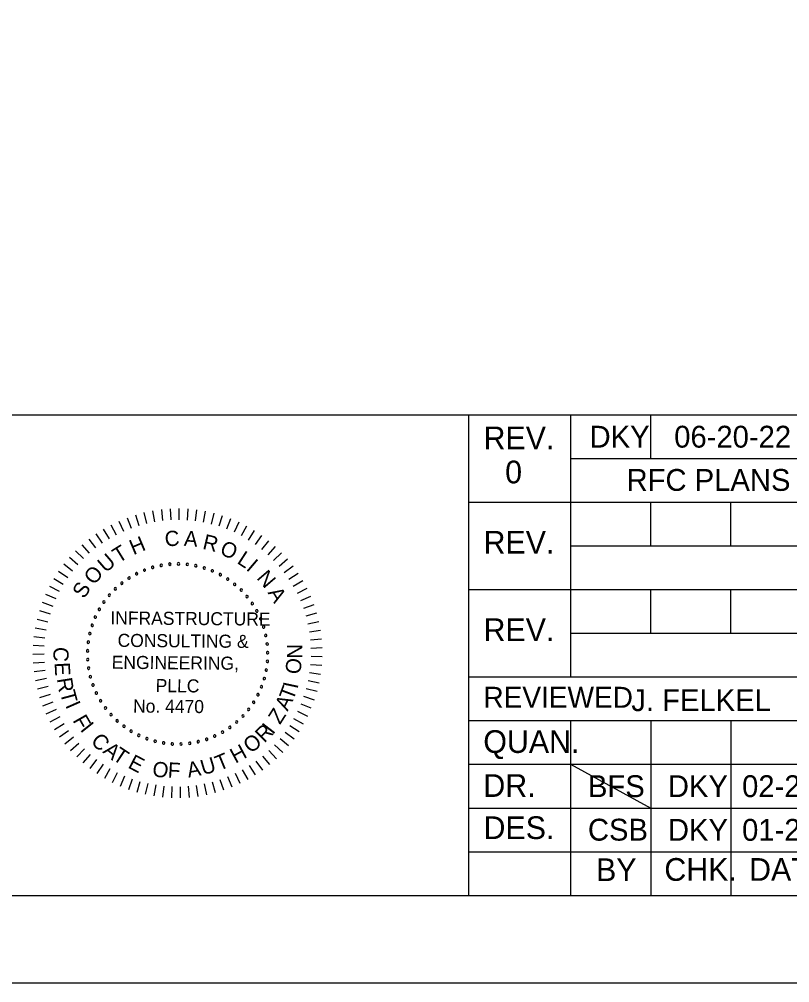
# Model space of a CAD drawing. Extents: x -133.1 to -97, y -1.7 to 20.3.
# Drawn here: x -107.71 to -103.3, y -1.69 to 3.82 of the extents above; entities that cross this region are included whole.
import ezdxf

# ---------------------------------------------------------------- set-up
doc = ezdxf.new("R2010")
doc.units = 0
for name, color, linetype in [('BR_BORDER LINES', 7, 'Continuous'), ('BR_TEXT', 7, 'Continuous'), ('Level 31', 7, 'Continuous')]:
    doc.layers.add(name, color=color, linetype=linetype)

msp = doc.modelspace()

# ---------------------------------------------------------------- linework, layer by layer
at = {"layer": 'BR_BORDER LINES'}
for p, q in [((-110.5071, 1.5591), (-105.1419, 1.5591)), ((-105.1419, -1.191), (-105.1419, 1.5591)), ((-105.1419, 1.5591), (-97.6416, 1.5591)), ((-104.5585, 1.5591), (-104.5585, 0.059)), ((-104.1002, 1.3091), (-104.1002, 1.5591)), ((-104.5585, 1.3091), (-103.0585, 1.3091)), ((-105.1419, 1.0591), (-103.0585, 1.0591)), ((-104.1002, 0.809), (-104.1002, 1.0591)), ((-103.6418, 0.809), (-103.6418, 1.0591)), ((-104.5585, 0.809), (-103.0585, 0.809)), ((-105.1419, 0.559), (-103.0585, 0.559)), ((-104.1002, 0.309), (-104.1002, 0.559)), ((-103.6418, 0.309), (-103.6418, 0.559)), ((-104.5585, 0.309), (-103.0585, 0.309)), ((-105.1419, 0.059), (-103.0585, 0.059)), ((-105.1419, -0.191), (-103.0585, -0.191)), ((-104.5585, -0.191), (-104.5585, -1.191)), ((-104.1002, -0.191), (-104.1002, -1.191)), ((-103.6418, -0.191), (-103.6418, -1.191)), ((-105.1419, -0.441), (-103.0585, -0.441)), ((-105.1419, -0.691), (-103.0585, -0.691)), ((-105.1419, -0.941), (-103.0585, -0.941)), ((-131.3076, -1.191), (-97.6416, -1.191))]:
    msp.add_line(p, q, dxfattribs=at)
at = {"layer": 'BR_TEXT'}
for p, q in [((-107.0007, 0.9998), (-106.9858, 0.9379)), ((-106.9512, 1.01), (-106.9401, 0.9473)), ((-106.9012, 1.0172), (-106.894, 0.9539)), ((-106.8509, 1.0213), (-106.8476, 0.9578)), ((-106.8005, 1.0224), (-106.801, 0.9587)), ((-106.75, 1.0204), (-106.7544, 0.9569)), ((-106.6998, 1.0153), (-106.7081, 0.9522)), ((-106.65, 1.0071), (-106.6621, 0.9446)), ((-106.6007, 0.996), (-106.6166, 0.9343)), ((-107.1439, 0.9513), (-107.1181, 0.8932)), ((-107.0972, 0.9704), (-107.0749, 0.9107)), ((-107.0494, 0.9866), (-107.0308, 0.9257)), ((-106.5523, 0.9818), (-106.5719, 0.9213)), ((-106.5048, 0.9648), (-106.528, 0.9055)), ((-106.4584, 0.9448), (-106.4852, 0.8871)), ((-107.2335, 0.9049), (-107.2008, 0.8503)), ((-107.1895, 0.9295), (-107.1601, 0.873)), ((-106.4133, 0.9221), (-106.4436, 0.8661)), ((-106.3697, 0.8967), (-106.4034, 0.8426)), ((-107.3168, 0.8478), (-107.2776, 0.7976)), ((-107.276, 0.8776), (-107.24, 0.8251)), ((-106.3277, 0.8686), (-106.3646, 0.8167)), ((-106.2875, 0.8381), (-106.3275, 0.7885)), ((-107.3925, 0.7811), (-107.3475, 0.736)), ((-107.3557, 0.8156), (-107.3135, 0.7679)), ((-106.2493, 0.8051), (-106.2922, 0.7581)), ((-107.4272, 0.7444), (-107.3795, 0.7022)), ((-106.2131, 0.7699), (-106.2588, 0.7256)), ((-106.1791, 0.7326), (-106.2275, 0.6911)), ((-107.4895, 0.665), (-107.437, 0.6289)), ((-107.4595, 0.7056), (-107.4094, 0.6664)), ((-106.1475, 0.6932), (-106.1983, 0.6548)), ((-107.5169, 0.6226), (-107.4623, 0.5897)), ((-106.1184, 0.652), (-106.1714, 0.6167)), ((-106.0918, 0.6091), (-106.1469, 0.5771)), ((-107.5416, 0.5786), (-107.4852, 0.5491)), ((-106.0679, 0.5646), (-106.1248, 0.5361)), ((-107.5637, 0.5332), (-107.5055, 0.5072)), ((-106.0467, 0.5188), (-106.1052, 0.4938)), ((-107.5829, 0.4865), (-107.5233, 0.4641)), ((-106.0283, 0.4718), (-106.0883, 0.4504)), ((-107.6126, 0.3901), (-107.5507, 0.3751)), ((-107.5992, 0.4387), (-107.5384, 0.42)), ((-106.0129, 0.4237), (-106.0741, 0.406)), ((-107.623, 0.3407), (-107.5604, 0.3295)), ((-106.0004, 0.3748), (-106.0625, 0.3608)), ((-107.6304, 0.2907), (-107.5672, 0.2834)), ((-105.9909, 0.3252), (-106.0538, 0.3151)), ((-107.6348, 0.2404), (-107.5712, 0.237)), ((-105.9845, 0.2751), (-106.0479, 0.2689)), ((-105.9811, 0.2247), (-106.0448, 0.2224)), ((-107.636, 0.19), (-107.5723, 0.1904)), ((-105.9809, 0.1743), (-106.0445, 0.1758)), ((-107.6342, 0.1395), (-107.5706, 0.1438)), ((-105.9836, 0.1239), (-106.0471, 0.1292)), ((-107.6293, 0.0893), (-107.5661, 0.0974)), ((-105.9895, 0.0737), (-106.0525, 0.0829)), ((-107.6213, 0.0394), (-107.5588, 0.0514)), ((-107.6103, -0.0099), (-107.5487, 0.0059)), ((-105.9984, 0.024), (-106.0607, 0.0371)), ((-107.5964, -0.0584), (-107.5358, -0.0388)), ((-106.0252, -0.0733), (-106.0855, -0.0527)), ((-106.0103, -0.025), (-106.0717, -0.0082)), ((-107.5795, -0.106), (-107.5202, -0.0828)), ((-106.043, -0.1205), (-106.1019, -0.0963)), ((-107.5597, -0.1524), (-107.5019, -0.1256)), ((-106.0636, -0.1666), (-106.1209, -0.1389)), ((-107.5371, -0.1976), (-107.4811, -0.1673)), ((-107.5119, -0.2413), (-107.4578, -0.2077)), ((-106.1131, -0.2545), (-106.1667, -0.22)), ((-106.087, -0.2113), (-106.1426, -0.1802)), ((-107.484, -0.2834), (-107.4321, -0.2465)), ((-106.1418, -0.2961), (-106.1931, -0.2584)), ((-107.4536, -0.3237), (-107.404, -0.2837)), ((-107.4208, -0.362), (-107.3737, -0.3191)), ((-106.2065, -0.3735), (-106.2529, -0.3299)), ((-106.173, -0.3358), (-106.2219, -0.2951)), ((-107.3857, -0.3983), (-107.3413, -0.3527)), ((-107.3485, -0.4324), (-107.307, -0.3841)), ((-106.2423, -0.4092), (-106.2859, -0.3628)), ((-107.3092, -0.4642), (-107.2708, -0.4135)), ((-107.2681, -0.4935), (-107.2328, -0.4405)), ((-106.32, -0.4736), (-106.3576, -0.4222)), ((-106.2801, -0.4426), (-106.3208, -0.3936)), ((-107.2253, -0.5203), (-107.1933, -0.4652)), ((-107.1809, -0.5444), (-107.1523, -0.4875)), ((-106.4498, -0.5513), (-106.4774, -0.4939)), ((-106.4049, -0.528), (-106.436, -0.4725)), ((-106.3616, -0.5021), (-106.3961, -0.4485)), ((-107.1352, -0.5657), (-107.1101, -0.5072)), ((-107.0882, -0.5842), (-107.0668, -0.5243)), ((-107.0402, -0.5998), (-107.0225, -0.5387)), ((-106.9913, -0.6125), (-106.9773, -0.5504)), ((-106.5915, -0.6041), (-106.6083, -0.5427)), ((-106.5432, -0.5894), (-106.5637, -0.5291)), ((-106.4959, -0.5718), (-106.52, -0.5128)), ((-106.9418, -0.6221), (-106.9316, -0.5593)), ((-106.8918, -0.6288), (-106.8854, -0.5654)), ((-106.8414, -0.6323), (-106.8389, -0.5687)), ((-106.7909, -0.6328), (-106.7923, -0.5691)), ((-106.7405, -0.6302), (-106.7458, -0.5667)), ((-106.6903, -0.6245), (-106.6995, -0.5615)), ((-106.6406, -0.6158), (-106.6536, -0.5535))]:
    msp.add_line(p, q, dxfattribs=at)
for centre, start, end in [((-106.9977, 0.6702), 21.6807, 201.6807), ((-106.9977, 0.6702), 201.6807, 21.6807), ((-106.9506, 0.6862), 16.1422, 196.1422), ((-106.9506, 0.6862), 196.1422, 16.1422), ((-106.9021, 0.6977), 10.6038, 190.6038), ((-106.9021, 0.6977), 190.6038, 10.6038), ((-106.8527, 0.7043), 5.0653, 185.0653), ((-106.8527, 0.7043), 185.0653, 5.0653), ((-106.8029, 0.7062), 359.5268, 179.5268), ((-106.8029, 0.7062), 179.5268, 359.5268), ((-106.7531, 0.7033), 173.9884, 353.9884), ((-106.7531, 0.7033), 353.9884, 173.9884), ((-106.7039, 0.6956), 168.4499, 348.4499), ((-106.7039, 0.6956), 348.4499, 168.4499), ((-106.6557, 0.6832), 162.9114, 342.9114), ((-106.6557, 0.6832), 342.9114, 162.9114), ((-106.6088, 0.6662), 157.373, 337.373), ((-106.6088, 0.6662), 337.373, 157.373), ((-107.0864, 0.6248), 32.7576, 212.7576), ((-107.0864, 0.6248), 212.7576, 32.7576), ((-107.0431, 0.6496), 27.2191, 207.2191), ((-107.0431, 0.6496), 207.2191, 27.2191), ((-106.5639, 0.6447), 151.8345, 331.8345), ((-106.5639, 0.6447), 331.8345, 151.8345), ((-106.5212, 0.619), 146.2961, 326.2961), ((-106.5212, 0.619), 326.2961, 146.2961), ((-107.1646, 0.5633), 43.8345, 223.8345), ((-107.1646, 0.5633), 223.8345, 43.8345), ((-107.127, 0.5959), 38.2961, 218.2961), ((-107.127, 0.5959), 218.2961, 38.2961), ((-106.4811, 0.5893), 140.7576, 320.7576), ((-106.4811, 0.5893), 320.7576, 140.7576), ((-106.4442, 0.5559), 135.2191, 315.2191), ((-106.4442, 0.5559), 315.2191, 135.2191), ((-107.1989, 0.5271), 49.373, 229.373), ((-107.1989, 0.5271), 229.373, 49.373), ((-106.4106, 0.5191), 129.6807, 309.6807), ((-106.4106, 0.5191), 309.6807, 129.6807), ((-107.2563, 0.4458), 60.4499, 240.4499), ((-107.2563, 0.4458), 240.4499, 60.4499), ((-107.2296, 0.4879), 54.9114, 234.9114), ((-107.2296, 0.4879), 234.9114, 54.9114), ((-106.3808, 0.4792), 124.1422, 304.1422), ((-106.3808, 0.4792), 304.1422, 124.1422), ((-106.3549, 0.4366), 118.6038, 298.6038), ((-106.3549, 0.4366), 298.6038, 118.6038), ((-107.2788, 0.4014), 65.9884, 245.9884), ((-107.2788, 0.4014), 245.9884, 65.9884), ((-106.3333, 0.3917), 113.0653, 293.0653), ((-106.3333, 0.3917), 293.0653, 113.0653), ((-107.297, 0.3549), 71.5268, 251.5268), ((-107.297, 0.3549), 251.5268, 71.5268), ((-106.3161, 0.3449), 107.5268, 287.5268), ((-106.3161, 0.3449), 287.5268, 107.5268), ((-107.3106, 0.307), 77.0653, 257.0653), ((-107.3106, 0.307), 257.0653, 77.0653), ((-106.3035, 0.2967), 101.9884, 281.9884), ((-106.3035, 0.2967), 281.9884, 101.9884), ((-107.3195, 0.258), 82.6038, 262.6038), ((-107.3195, 0.258), 262.6038, 82.6038), ((-106.2956, 0.2475), 96.4499, 276.4499), ((-106.2956, 0.2475), 276.4499, 96.4499), ((-107.3236, 0.2083), 88.1422, 268.1422), ((-107.3229, 0.1585), 93.6807, 273.6807), ((-107.3236, 0.2083), 268.1422, 88.1422), ((-107.3229, 0.1585), 273.6807, 93.6807), ((-106.2925, 0.1977), 90.9114, 270.9114), ((-106.2925, 0.1977), 270.9114, 90.9114), ((-107.3174, 0.109), 99.2191, 279.2191), ((-107.3174, 0.109), 279.2191, 99.2191), ((-106.2942, 0.1479), 85.373, 265.373), ((-106.2942, 0.1479), 265.373, 85.373), ((-107.3071, 0.0602), 104.7576, 284.7576), ((-107.3071, 0.0602), 284.7576, 104.7576), ((-106.312, 0.05), 74.2961, 254.2961), ((-106.312, 0.05), 254.2961, 74.2961), ((-106.3007, 0.0985), 79.8345, 259.8345), ((-106.3007, 0.0985), 259.8345, 79.8345), ((-107.2922, 0.0126), 110.2961, 290.2961), ((-107.2922, 0.0126), 290.2961, 110.2961), ((-106.3279, 0.0028), 68.7576, 248.7576), ((-106.3279, 0.0028), 248.7576, 68.7576), ((-107.2728, -0.0332), 115.8345, 295.8345), ((-107.2728, -0.0332), 295.8345, 115.8345), ((-106.3483, -0.0427), 63.2191, 243.2191), ((-106.3483, -0.0427), 243.2191, 63.2191), ((-107.249, -0.077), 121.373, 301.373), ((-107.249, -0.077), 301.373, 121.373), ((-106.3729, -0.086), 57.6807, 237.6807), ((-106.3729, -0.086), 237.6807, 57.6807), ((-107.2211, -0.1183), 126.9114, 306.9114), ((-107.2211, -0.1183), 306.9114, 126.9114), ((-107.1894, -0.1567), 132.4499, 312.4499), ((-107.1894, -0.1567), 312.4499, 132.4499), ((-106.4342, -0.1645), 46.6038, 226.6038), ((-106.4342, -0.1645), 226.6038, 46.6038), ((-106.4016, -0.1267), 52.1422, 232.1422), ((-106.4016, -0.1267), 232.1422, 52.1422), ((-107.1541, -0.1919), 137.9884, 317.9884), ((-107.1541, -0.1919), 317.9884, 137.9884), ((-107.1156, -0.2235), 143.5268, 323.5268), ((-107.1156, -0.2235), 323.5268, 143.5268), ((-106.4702, -0.1989), 41.0653, 221.0653), ((-106.4702, -0.1989), 221.0653, 41.0653), ((-107.0742, -0.2512), 149.0653, 329.0653), ((-107.0742, -0.2512), 329.0653, 149.0653), ((-107.0303, -0.2749), 154.6038, 334.6038), ((-107.0303, -0.2749), 334.6038, 154.6038), ((-106.5957, -0.2793), 24.4499, 204.4499), ((-106.5513, -0.2566), 29.9884, 209.9884), ((-106.5513, -0.2566), 209.9884, 29.9884), ((-106.5093, -0.2297), 35.5268, 215.5268), ((-106.5093, -0.2297), 215.5268, 35.5268), ((-106.9843, -0.2941), 160.1422, 340.1422), ((-106.9843, -0.2941), 340.1422, 160.1422), ((-106.9367, -0.3089), 165.6807, 345.6807), ((-106.9367, -0.3089), 345.6807, 165.6807), ((-106.8879, -0.3189), 171.2191, 351.2191), ((-106.8879, -0.3189), 351.2191, 171.2191), ((-106.8384, -0.3242), 356.7576, 176.7576), ((-106.8384, -0.3242), 176.7576, 356.7576), ((-106.7885, -0.3248), 2.2961, 182.2961), ((-106.7885, -0.3248), 182.2961, 2.2961), ((-106.7389, -0.3205), 7.8345, 187.8345), ((-106.7389, -0.3205), 187.8345, 7.8345), ((-106.6899, -0.3114), 13.373, 193.373), ((-106.6899, -0.3114), 193.373, 13.373), ((-106.642, -0.2976), 18.9114, 198.9114), ((-106.642, -0.2976), 198.9114, 18.9114), ((-106.5957, -0.2793), 204.4499, 24.4499)]:
    msp.add_arc(centre, 0.00701, start, end, dxfattribs=at)
at = {"layer": 'Level 31'}
msp.add_line((-104.5585, -0.441), (-104.1002, -0.691), dxfattribs=at)
msp.add_lwpolyline([(-133.1409, -1.691), (-97.141, -1.691), (-97.141, 20.309), (-133.1409, 20.309)], close=True, dxfattribs=at)

# ---------------------------------------------------------------- texts
at = {"layer": 'BR_TEXT'}
for s, height, p in [('REV.', 0.13001, (-105.0572, 1.362)), ('DKY', 0.12499, (-104.4502, 1.3715)), ('06-20-22', 0.12499, (-103.9658, 1.3715)), ('0', 0.13, (-104.9333, 1.167)), ('RFC PLANS', 0.12499, (-104.2386, 1.124)), ('REV.', 0.13001, (-105.0572, 0.7645)), ('REV.', 0.13001, (-105.0572, 0.2644)), ('REVIEWED', 0.12, (-105.0579, -0.1175)), ('J. FELKEL', 0.125, (-104.2114, -0.1366)), ('QUAN.', 0.13001, (-105.0585, -0.3758)), ('DR.', 0.13001, (-105.0583, -0.6274)), ('BFS', 0.12499, (-104.4595, -0.6286)), ('DKY', 0.12499, (-104.002, -0.6286)), ('02-22', 0.12499, (-103.5772, -0.6286)), ('DES.', 0.13001, (-105.0572, -0.8687)), ('CSB', 0.12499, (-104.4598, -0.8776)), ('DKY', 0.12499, (-104.0017, -0.8786)), ('01-22', 0.12499, (-103.5772, -0.8786)), ('BY', 0.13001, (-104.4132, -1.109)), ('CHK.', 0.13001, (-104.0224, -1.1077)), ('DATE', 0.13001, (-103.5372, -1.1076))]:
    msp.add_text(s, height=height, dxfattribs=at).set_placement(p)
for s, height, rotation, p in [('C', 0.0872, 4.7281, (-106.8784, 0.8048)), ('A', 0.0872, 355.6981, (-106.7739, 0.8098)), ('H', 0.0872, 22.7882, (-107.0612, 0.7554)), ('R', 0.0872, 346.6681, (-106.6696, 0.7928)), ('O', 0.0872, 337.638, (-106.5719, 0.763)), ('T', 0.0872, 31.8182, (-107.1461, 0.7078)), ('L', 0.0872, 327.108, (-106.4731, 0.7125)), ('U', 0.0872, 40.8482, (-107.2194, 0.6516)), ('I', 0.0872, 319.578, (-106.4205, 0.6747)), ('O', 0.0872, 49.8782, (-107.2864, 0.5806)), ('N', 0.0872, 310.548, (-106.3597, 0.6239)), ('S', 0.0872, 58.9083, (-107.3418, 0.5024)), ('A', 0.0872, 301.5179, (-106.2946, 0.5415)), ('INFRASTRUCTURE', 0.074771, 359.5268, (-107.1932, 0.3599)), ('CONSULTING &', 0.074771, 359.5268, (-107.1519, 0.2313)), ('C', 0.0872, 267.025, (-107.5168, 0.2325)), ('N', 0.0872, 89.2085, (-106.0953, 0.1628)), ('ENGINEERING,', 0.074771, 359.5268, (-107.1855, 0.1059)), ('E', 0.0872, 273.025, (-107.5124, 0.1409)), ('O', 0.0872, 83.2085, (-106.1064, 0.0713)), ('R', 0.0872, 279.025, (-107.4996, 0.0487)), ('PLLC', 0.07477, 359.5268, (-106.9338, -0.0277)), ('T', 0.0872, 69.3954, (-106.1476, -0.0805)), ('I', 0.0872, 77.9093, (-106.1219, -0.013)), ('T', 0.0872, 285.025, (-107.4822, -0.0301)), ('I', 0.0872, 293.7713, (-107.4525, -0.1032)), ('No. 4470', 0.07477, 359.5268, (-107.0633, -0.1446)), ('A', 0.0872, 63.3954, (-106.1784, -0.1408)), ('F', 0.0872, 299.7713, (-107.4113, -0.1893)), ('Z', 0.0872, 57.3954, (-106.2222, -0.2172)), ('I', 0.0872, 308.5268, (-107.3692, -0.2431)), ('R', 0.0872, 44.5268, (-106.3127, -0.3221)), ('I', 0.0872, 52.3339, (-106.2633, -0.2748)), ('C', 0.0872, 314.5268, (-107.3099, -0.3133)), ('O', 0.0872, 38.5268, (-106.3893, -0.3821)), ('A', 0.0872, 320.5268, (-107.2407, -0.3718)), ('H', 0.0872, 28.5268, (-106.4774, -0.4381)), ('T', 0.0872, 326.5268, (-107.1863, -0.4103)), ('E', 0.0872, 332.5268, (-107.0977, -0.4581)), ('T', 0.0872, 22.5268, (-106.5706, -0.4799)), ('O', 0.0872, 350.5268, (-106.9576, -0.507)), ('F', 0.0872, 356.5268, (-106.8661, -0.5161)), ('A', 0.0872, 10.5268, (-106.7462, -0.5177)), ('U', 0.0872, 16.5268, (-106.6623, -0.5042))]:
    msp.add_text(s, height=height, rotation=rotation, dxfattribs=at).set_placement(p)

doc.saveas('drawing.dxf')
